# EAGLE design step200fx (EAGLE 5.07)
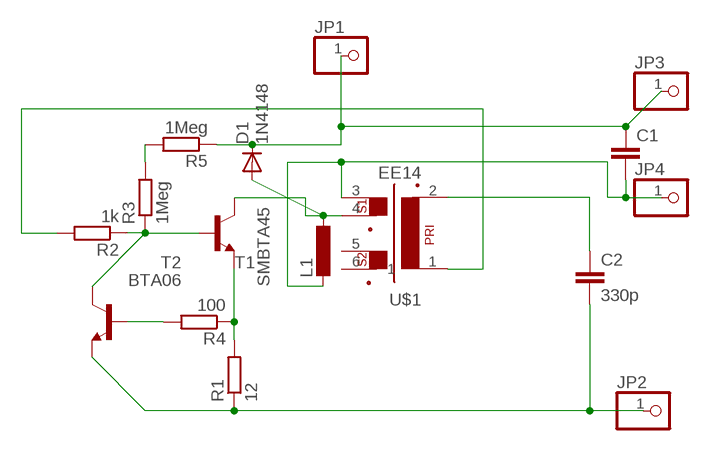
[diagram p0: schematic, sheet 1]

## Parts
C1  C-EU025-025X050  [C025-025X050]
C2  330p  C-EUC0805  [C0805]
D1  1N4148  DIODE-SMA-DO214  [SMA-DO214AC]
JP1  PINHD-1X11MM6  [1X1MM8]
JP2  PINHD-1X11MM6  [1X1MM8]
JP3  PINHD-1X11X0.4  [1X01]
JP4  PINHD-1X11X0.4  [1X01]
L1  L-EU0204/5  [0204/5]
R1  12  R-EU_R0805  [R0805]
R2  1k  R-EU_R0805  [R0805]
R3  1Meg  R-EU_R1206  [R1206]
R4  100  R-EU_R0805  [R0805]
R5  1Meg  R-EU_R1206  [R1206]
T1  SMBTA45  BC848  [SOT23]
T2  BTA06  BC848  [SOT23]
U$1  EE14  [EE14]

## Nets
B1C2: R2.1 R3.1 T1.B T2.C
C1: D1.A L1.1 T1.C U$1.4
EB: R1.2 R4.1 T1.E
N$1: R3.2 R5.2
N$2: R4.2 T2.B
N$4: R2.2 U$1.1
N$6: C2.1 U$1.2
OUT-: C1.2 JP4.1 L1.2 U$1.3
V+: C1.1 D1.K(C) JP1.1 JP3.1 R5.1
V-: C2.2 JP2.1 R1.1 T2.E
Unconnected: U$1.5 U$1.6

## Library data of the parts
C1 C2 = rcl:C-EU: CAPACITOR, European symbol
D1 = diode:DIODE-: DIODE
JP1-JP4 = pinhead:PINHD-1X1: PIN HEADER
L1 = rcl:L-EU: INDUCTOR, European symbol
R1-R5 = rcl:R-EU_: RESISTOR, European symbol
T1 T2 = transistor:BC848: NPN TRANSISTOR
U$1 = trafo:EE14

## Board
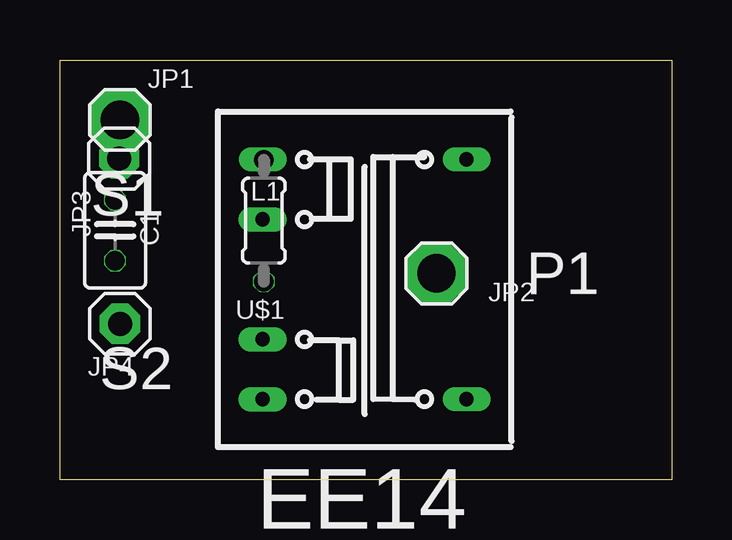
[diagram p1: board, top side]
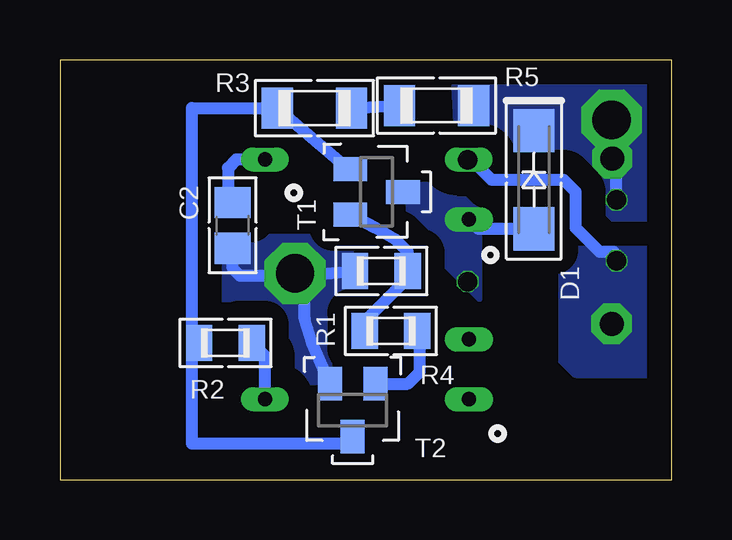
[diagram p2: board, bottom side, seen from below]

Size 25.5 x 17.5 mm. Coordinates in mm from the lower left corner, seen from the top.
Outline: 0,17.5 25.5,17.5 25.5,0 0,0 0,17.5
Copper layers (1*16): Top 0.035mm / dielectric 1.5mm / Bottom 0.035mm
Design rules "default": minimum track width 10mil, minimum drill 20mil, track to track 8mil, track to pad 8mil, pad to pad 8mil, via to via 8mil, smd to smd 8mil, copper to edge 40mil, drill to drill 8mil, minimum pad ring 1mil, minimum via ring 8mil, stop-mask expansion 4mil, vias tented up to drill 0mil, thermal gap 10mil

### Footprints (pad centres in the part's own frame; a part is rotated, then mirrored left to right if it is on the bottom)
C025-025X050 = drill 0.813 octagon: 1 -1.27,0; 2 1.27,0
C0805 = smd 1.3 x 1.5: 1 -0.95,0; 2 0.95,0
SMA-DO214AC = smd 1.8 x 1.7: A 2.05,-0.127; K -2.05,-0.127
1X1MM8 = drill 1.6 pad 2.54 octagon: 1 0,0
1X01 = drill 1 pad 1.676 octagon: 1 0,0
0204/5 = drill 0.813 octagon: 1 -2.54,0; 2 2.54,0
R0805 = smd 1.1 x 1.5: 1 -1.1,0; 2 1.1,0
R1206 = smd 1.3 x 1.7: 1 -1.55,0; 2 1.55,0
SOT23 = smd 1 x 1.4: B -0.95,-1.1; C 0,1.1; E 0.95,-1.1
EE14 = drill 0.6 pad 1 long: 1 4.25,-5; 2 4.25,5; 3 -4.25,5 | drill 0.6 pad 1.016 long: 4 -4.25,2.5; 5 -4.25,-2.5; 6 -4.25,-5

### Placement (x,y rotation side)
C1  2.3,10.39 270 top
C2  18.3,10.6 270 bottom
D1  5.61,12.51 270 bottom
JP1  2.5,15 0 top
JP2  15.7,8.6 0 top
JP3  2.47,13.39 0 top
JP4  2.5,6.5 0 top
L1  8.5,10.8 90 top
R1  12.1,8.7 0 bottom
R2  18.6,5.7 0 bottom
R3  14.89,15.49 0 bottom
R4  11.7,6.2 0 bottom
R5  9.8,15.6 180 bottom
T1  12.3,12 270 bottom
T2  13.3,2.9 180 bottom
U$1  12.7,8.35 0 top

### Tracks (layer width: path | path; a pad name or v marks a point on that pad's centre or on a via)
B1C2
  Bottom 0.5: T1.B 13.6,13.05 R3.1 19.99,15.49 20,15.5 20,6 R2.1 20,5.4 20,1.5 13.6,1.5 T2.C
C1
  Bottom 0.5: D1.A 8.05,10.46 U$1.4
  pour Bottom (isolate 1, rank 3, no thermals): 8,12.3 11,12.3 11,10.5 8,7.5
EB
  Bottom 0.5: R4.1 12.6,6.4 12.6,6.8 11,8.4 R1.2 11,9.5 11.5,10 12.35,10.5 T1.E
N$1
  Bottom 0.5: R5.2 12.93,15.5 R3.2
N$2
  Bottom 0.5: T2.B 11,4 10.5,4.5 10.5,6.1 R4.2
N$4
  Bottom 0.5: U$1.1 16.95,5.15 R2.2
N$6
  Bottom 0.5: U$1.2 18.15,13.35 18.5,13 18.5,11.75 C2.1
OUT-
  Bottom 0.5: C1.2 2.42,9.5 3,9.5 4,10.5 4,12 4.5,12.5 7.5,12.5 8.35,13.35 U$1.3 L1.2
  pour Bottom (isolate 1, rank 2, no thermals): 1,9.5 4.5,9.5 4.5,5 4,4.5 1,4.5
V+
  Bottom 0.5: C1.1 2.3,13.22 JP3.1
  pour Bottom (isolate 1, rank 4, no thermals): 0.5,16.5 6,16.5 8.1,16.4 9.1,16.4 9,14.5 9.5,13.5 4,13.5 4,11 3.5,10.5 0.5,10.5
V-
  Bottom 0.5: T2.E 15,5.7 15.3,6.7 15.3,8.2 JP2.1 | C2.2 18.3,8.8 18,8.5 15.8,8.5 JP2.1 | R1.1 15.6,8.5 JP2.1
  pour Bottom (isolate 1, rank 2, no thermals): 13.5,10 19,10 19,7 16,4 15,4 13.5,5.5 13.5,7.5 13.5,9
